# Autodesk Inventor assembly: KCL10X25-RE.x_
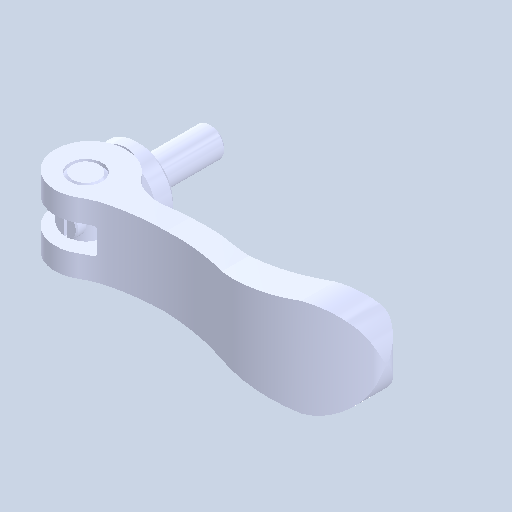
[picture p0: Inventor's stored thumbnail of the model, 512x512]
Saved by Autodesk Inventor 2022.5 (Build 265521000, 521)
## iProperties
Created: 2024-08
Part Number: KCL10X25-RE.x_
Document SubType Name: Assembly
Designer: ImaoCorp
Author: ImaoCorp
Sending System: SOLIDWORKS 2022-2022290
MC: AMD64
MC_MODEL: Intel64 Family 6 Model 60 Stepping 3, GenuineIntel
OS: Windows_NT
FRU: Parasolid Version 33.1, build 260,  4-25-2022
FORMAT: text
GUISE: transmit
KEY: FILEKCL10X25-RE.x_t
DATE: Thu Aug 29 10:50:51 2024
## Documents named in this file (5)
- Y:\5.更新分\2024年対応\1001_KCL\データ\kcl10x25-re\KCL10X25-RE.x_.iam
- Y:\5.更新分\2024年対応\1001_KCL\データ\kcl10x25-re\KCL10X25-RE_01.ipt
- Y:\5.更新分\2024年対応\1001_KCL\データ\kcl10x25-re\KCL10X25-RE_02.ipt
- Y:\5.更新分\2024年対応\1001_KCL\データ\kcl10x25-re\KCL10X25-RE_03.ipt
- Y:\5.更新分\2024年対応\1001_KCL\データ\kcl10x25-re\KCL10X25-RE_04.ipt
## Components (4 placed, 4 different names)
1. KCL10X25-RE_01
2. KCL10X25-RE_02
3. KCL10X25-RE_03
4. KCL10X25-RE_04
